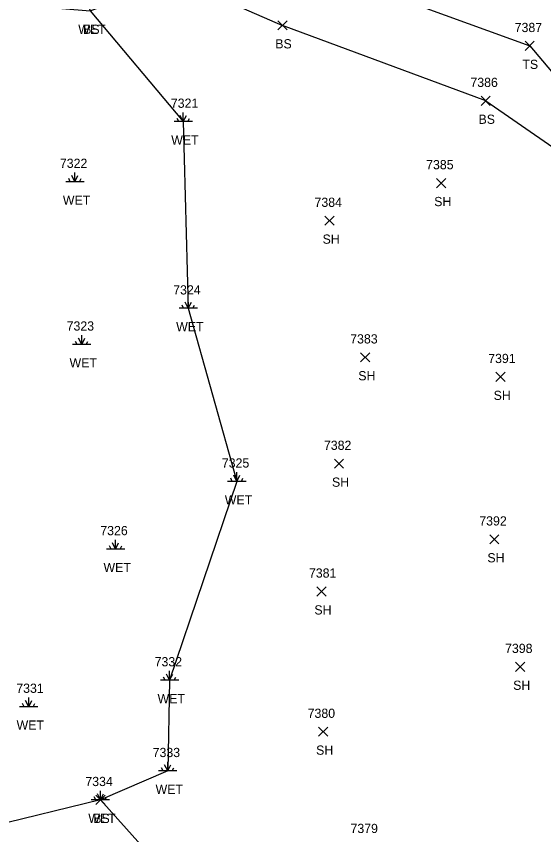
# Model space of a CAD drawing. Extents: x 1472233 to 1475777, y 540726 to 543442.
# Drawn here: x 1472633.6 to 1472747.9, y 540836.4 to 541014 of the extents above; entities that cross this region are included whole.
import ezdxf

# ---------------------------------------------------------------- set-up
doc = ezdxf.new("R2010")
doc.units = 0
for name, color, linetype in [('L_A', 7, 'Continuous'), ('L_I', 7, 'Continuous'), ('L_TIC', 7, 'Continuous'), ('LELB', 7, 'Continuous'), ('LWET', 7, 'Continuous')]:
    doc.layers.add(name, color=color, linetype=linetype)

msp = doc.modelspace()

# ---------------------------------------------------------------- linework, layer by layer
at = {"layer": 'L_TIC'}
for points in [[(1472690.25, 541011.03), (1472692.25, 541013.03)], [(1472692.25, 541011.03), (1472690.25, 541013.03)], [(1472743.87, 541006.57), (1472745.87, 541008.57)], [(1472745.87, 541006.57), (1472743.87, 541008.57)], [(1472734.33, 540994.66), (1472736.33, 540996.66)], [(1472736.33, 540994.66), (1472734.33, 540996.66)], [(1472724.67, 540976.8), (1472726.67, 540978.8)], [(1472726.67, 540976.8), (1472724.67, 540978.8)], [(1472700.47, 540968.64), (1472702.47, 540970.64)], [(1472702.47, 540968.64), (1472700.47, 540970.64)], [(1472708.21, 540939), (1472710.21, 540941)], [(1472710.21, 540939), (1472708.21, 540941)], [(1472737.56, 540934.75), (1472739.56, 540936.75)], [(1472739.56, 540934.75), (1472737.56, 540936.75)], [(1472702.51, 540915.91), (1472704.51, 540917.91)], [(1472704.51, 540915.91), (1472702.51, 540917.91)], [(1472736.2, 540899.5), (1472738.2, 540901.5)], [(1472738.2, 540899.5), (1472736.2, 540901.5)], [(1472698.7, 540888.19), (1472700.7, 540890.19)], [(1472700.7, 540888.19), (1472698.7, 540890.19)], [(1472741.79, 540871.84), (1472743.79, 540873.84)], [(1472743.79, 540871.84), (1472741.79, 540873.84)], [(1472699.07, 540857.76), (1472701.07, 540859.76)], [(1472701.07, 540857.76), (1472699.07, 540859.76)], [(1472650.78, 540842.96), (1472652.78, 540844.96)], [(1472652.78, 540842.96), (1472650.78, 540844.96)]]:
    msp.add_lwpolyline(points, dxfattribs=at)
at = {"layer": 'LELB'}
for points in [[(1472635.49, 541304.38), (1472635.4, 541287.09), (1472639.25, 541266.91), (1472635.07, 541251.65), (1472620.06, 541236.88), (1472619.74, 541221), (1472611.61, 541206.87), (1472612.68, 541174.42), (1472603.82, 541140.59), (1472615.26, 541104.88), (1472631.44, 541065.69), (1472649.59, 541015.19), (1472668.21, 541022.13), (1472691.25, 541012.03)], [(1472635.4, 541287.09), (1472645.61, 541269.82), (1472641.53, 541243.93), (1472627.92, 541237.01), (1472626.9, 541217.8), (1472627.61, 541201.05), (1472627.16, 541165.43), (1472614.45, 541140.86), (1472628.77, 541112.15), (1472641.98, 541074.45), (1472699.8, 541024.04), (1472744.87, 541007.57), (1472760.97, 540988.57), (1472777.56, 540981.86), (1472785.51, 540968.17), (1472789.6, 540958.75), (1472787.49, 540948.26)], [(1472735.33, 540995.66), (1472691.25, 541012.03)], [(1472735.33, 540995.66), (1472757.61, 540980.27), (1472773.72, 540979.74), (1472783.22, 540961.57), (1472783.78, 540960.58), (1472784.39, 540958.19), (1472787.49, 540948.26), (1472795.8, 540938.09)], [(1472651.78, 540843.96), (1472674.91, 540818.12), (1472694.76, 540805.62), (1472708.33, 540789.91), (1472741.58, 540795.37), (1472770.49, 540820.96), (1472783.7, 540838.39), (1472787.22, 540848.31), (1472797.88, 540881.67), (1472806.92, 540889.43), (1472810.65, 540895.67), (1472811.7, 540897.8), (1472809.33, 540901.95)]]:
    msp.add_lwpolyline(points, dxfattribs=at)
at = {"layer": 'LWET'}
for p, q in [((1472669.76, 540991.14), (1472669.09, 540992.47)), ((1472669.76, 540991.14), (1472669.76, 540993.14)), ((1472669.76, 540991.14), (1472670.42, 540992.47)), ((1472671.76, 540991.14), (1472667.76, 540991.14)), ((1472668.76, 540991.14), (1472668.42, 540991.81)), ((1472670.76, 540991.14), (1472671.09, 540991.81)), ((1472646.26, 540978.1), (1472646.26, 540980.1)), ((1472645.26, 540978.1), (1472644.92, 540978.77)), ((1472646.26, 540978.1), (1472645.59, 540979.44)), ((1472646.26, 540978.1), (1472646.92, 540979.44)), ((1472647.26, 540978.1), (1472647.59, 540978.77)), ((1472648.26, 540978.1), (1472644.26, 540978.1)), ((1472670.83, 540950.63), (1472670.17, 540951.96)), ((1472670.83, 540950.63), (1472670.83, 540952.63)), ((1472670.83, 540950.63), (1472671.5, 540951.96)), ((1472672.83, 540950.63), (1472668.83, 540950.63)), ((1472669.83, 540950.63), (1472669.5, 540951.3)), ((1472671.83, 540950.63), (1472672.17, 540951.3)), ((1472647.72, 540942.8), (1472647.72, 540944.8)), ((1472649.72, 540942.8), (1472645.72, 540942.8)), ((1472646.72, 540942.8), (1472646.38, 540943.46)), ((1472647.72, 540942.8), (1472647.05, 540944.13)), ((1472647.72, 540942.8), (1472648.38, 540944.13)), ((1472648.72, 540942.8), (1472649.05, 540943.46)), ((1472681.37, 540913.07), (1472680.7, 540914.4)), ((1472681.37, 540913.07), (1472681.37, 540915.07)), ((1472681.37, 540913.07), (1472682.04, 540914.4)), ((1472683.37, 540913.07), (1472679.37, 540913.07)), ((1472680.37, 540913.07), (1472680.04, 540913.74)), ((1472682.37, 540913.07), (1472682.7, 540913.74)), ((1472655.08, 540898.4), (1472655.08, 540900.4)), ((1472657.08, 540898.4), (1472653.08, 540898.4)), ((1472654.08, 540898.4), (1472653.74, 540899.07)), ((1472655.08, 540898.4), (1472654.41, 540899.73)), ((1472655.08, 540898.4), (1472655.74, 540899.73)), ((1472656.08, 540898.4), (1472656.41, 540899.07)), ((1472666.8, 540869.94), (1472666.8, 540871.94)), ((1472668.8, 540869.94), (1472664.8, 540869.94)), ((1472665.8, 540869.94), (1472665.46, 540870.61)), ((1472666.8, 540869.94), (1472666.13, 540871.27)), ((1472666.8, 540869.94), (1472667.46, 540871.27)), ((1472667.8, 540869.94), (1472668.13, 540870.61)), ((1472635.23, 540864.19), (1472634.9, 540864.86)), ((1472636.23, 540864.19), (1472635.56, 540865.53)), ((1472636.23, 540864.19), (1472636.23, 540866.19)), ((1472636.23, 540864.19), (1472636.9, 540865.53)), ((1472637.23, 540864.19), (1472637.56, 540864.86)), ((1472638.23, 540864.19), (1472634.23, 540864.19)), ((1472666.37, 540850.25), (1472666.37, 540852.25)), ((1472665.37, 540850.25), (1472665.03, 540850.92)), ((1472666.37, 540850.25), (1472665.7, 540851.59)), ((1472666.37, 540850.25), (1472667.03, 540851.59)), ((1472667.37, 540850.25), (1472667.7, 540850.92)), ((1472668.37, 540850.25), (1472664.37, 540850.25)), ((1472651.78, 540843.96), (1472651.12, 540845.3)), ((1472651.78, 540843.96), (1472651.78, 540845.96)), ((1472651.78, 540843.96), (1472652.45, 540845.3)), ((1472653.78, 540843.96), (1472649.78, 540843.96)), ((1472650.78, 540843.96), (1472650.45, 540844.63)), ((1472652.78, 540843.96), (1472653.12, 540844.63))]:
    msp.add_line(p, q, dxfattribs=at)
msp.add_lwpolyline([(1472509.02, 540936.23), (1472540.74, 540955.61), (1472546.48, 540979.95), (1472576.24, 540992.8), (1472590.12, 540990.47), (1472604.5, 541000.5), (1472609.98, 541018.49), (1472649.59, 541015.19), (1472669.76, 540991.14), (1472670.83, 540950.63), (1472681.37, 540913.07), (1472666.8, 540869.94), (1472666.37, 540850.25), (1472651.78, 540843.96), (1472628.11, 540838.22), (1472591.21, 540836.7)], dxfattribs=at)

# ---------------------------------------------------------------- texts
at = {"layer": 'L_A'}
for s, p in [('WET', (1472646.97, 541010.19)), ('BS', (1472648.04, 541010.19)), ('BS', (1472689.7, 541007.03)), ('TS', (1472743.28, 541002.57)), ('BS', (1472733.77, 540990.66)), ('WET', (1472667.14, 540986.14)), ('WET', (1472643.64, 540973.1)), ('SH', (1472724.16, 540972.8)), ('SH', (1472699.96, 540964.64)), ('WET', (1472668.21, 540945.63)), ('WET', (1472645.09, 540937.8)), ('SH', (1472707.7, 540935)), ('SH', (1472737.05, 540930.75)), ('SH', (1472702, 540911.91)), ('WET', (1472678.75, 540908.07)), ('SH', (1472735.69, 540895.5)), ('WET', (1472652.45, 540893.4)), ('SH', (1472698.18, 540884.19)), ('SH', (1472741.28, 540867.84)), ('WET', (1472664.17, 540864.94)), ('WET', (1472633.61, 540859.19)), ('SH', (1472698.56, 540853.76)), ('WET', (1472663.75, 540845.25)), ('WET', (1472649.16, 540838.96)), ('BS', (1472650.23, 540838.96))]:
    msp.add_text(s, height=2, dxfattribs=at).set_placement(p)
at = {"layer": 'L_I'}
for s, p in [('7387', (1472741.61, 541010.57)), ('7386', (1472732.01, 540998.66)), ('7321', (1472667.06, 540994.14)), ('7322', (1472643, 540981.1)), ('7385', (1472722.41, 540980.8)), ('7384', (1472698.21, 540972.64)), ('7324', (1472667.57, 540953.63)), ('7323', (1472644.46, 540945.8)), ('7383', (1472705.95, 540943)), ('7391', (1472735.87, 540938.75)), ('7382', (1472700.25, 540919.91)), ('7325', (1472678.11, 540916.07)), ('7392', (1472733.94, 540903.5)), ('7326', (1472651.76, 540901.4)), ('7381', (1472697, 540892.19)), ('7398', (1472739.53, 540875.84)), ('7332', (1472663.54, 540872.94)), ('7331', (1472633.54, 540867.19)), ('7380', (1472696.72, 540861.76)), ('7333', (1472663.11, 540853.25)), ('7334', (1472648.52, 540846.96)), ('7334', (1472648.52, 540846.96)), ('7379', (1472706.01, 540836.77))]:
    msp.add_text(s, height=2, dxfattribs=at).set_placement(p)

doc.saveas('drawing.dxf')
